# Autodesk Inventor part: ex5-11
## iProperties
Shininess: 64.0
Length Units: 11272
Angle Units: 11279
Time Units: 11290
Mass Units: 11286
Length Display Precision: 3
Angle Display Precision: 2
Compacted: True
Part Number: ex5-11
Document SubType Name: Modeling
Created: 2002-09
Designer: Elise Moss
Density: 0.0
Volumn: 0.0
Area: 0.0
PropertySet Name: Model Information
Control State: 0
Master: False
Checked Out: False
Author: Elise Moss
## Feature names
1. Revolution1
2. Hole1
3. Shell1
4. Loft1
5. Sweep1
6. Coil1
7. Fillet1
8. Rib Chamfer [Chamfer]
